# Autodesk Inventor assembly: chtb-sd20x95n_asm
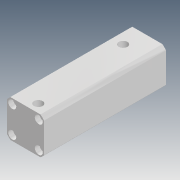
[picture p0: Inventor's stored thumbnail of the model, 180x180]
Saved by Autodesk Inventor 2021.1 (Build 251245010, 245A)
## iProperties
Company: Microsoft
Created: 2018-04
Part Number: chtb-sd20x95n_asm
Description: STEP AP214
Document SubType Name: Assembly
Designer: user
Title: chtb-sd20x95n_asm.STEP
Author: Windows
Revision Number: ÈÎºÎ
Sending System: SolidWorks 2015
Preprocessor: SwSTEP 2.0
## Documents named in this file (4)
- D:\Vault_2016\Projekty\Clamptek\Hydraulic\CHTB\CHTB-20\Inventor\CHTB-SD20x95N\chtb-sd20x95n_asm.iam
- D:\Vault_2016\Projekty\Clamptek\Hydraulic\CHTB\CHTB-20\Inventor\CHTB-SD20x95N\CHTB-SD20X95NBT.ipt
- D:\Vault_2016\Projekty\Clamptek\Hydraulic\CHTB\CHTB-20\Inventor\CHTB-SD20x95N\CHTB-SD20X95NHSG.ipt
- D:\Vault_2016\Projekty\Clamptek\Hydraulic\CHTB\CHTB-20\Inventor\CHTB-SD20x95N\QG.ipt
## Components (3 placed, 3 different names)
1. CHTB-SD20X95NBT_1
2. CHTB-SD20X95NHSG_2
3. QG_3
